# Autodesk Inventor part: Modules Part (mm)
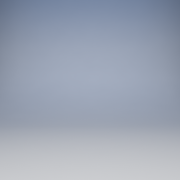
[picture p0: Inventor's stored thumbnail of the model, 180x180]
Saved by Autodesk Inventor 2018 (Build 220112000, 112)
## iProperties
Created: 2014-08
Part Number: Modules Part (mm)
Material: Generic
Document SubType Name: Modeling
Designer: Wally
Density: 1 g/cm^3
Appearance: Default
Author: Wally
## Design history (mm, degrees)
node "Sketch1"
